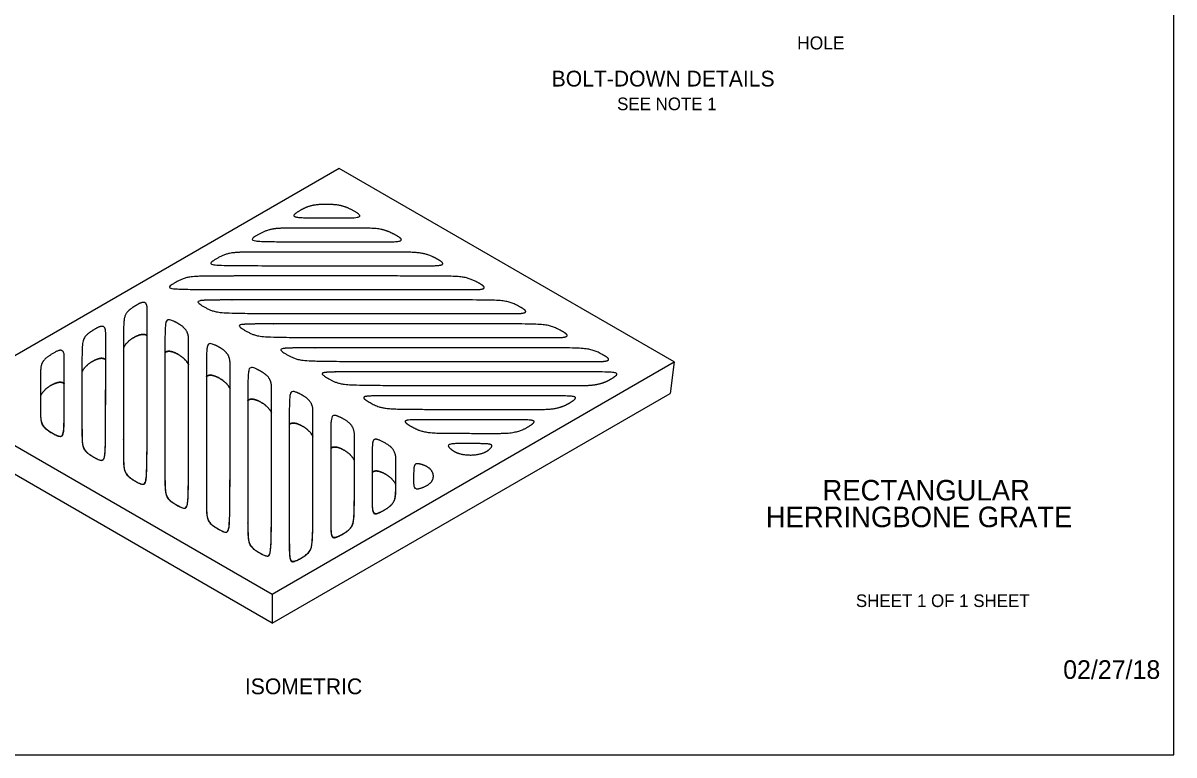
# Model space of a CAD drawing. Extents: x 99862 to 103151, y 100000 to 102076.
# Drawn here: x 101693 to 103151, y 100000 to 100926 of the extents above; entities that cross this region are included whole.
import ezdxf

# ---------------------------------------------------------------- set-up
doc = ezdxf.new("R2010")
doc.units = 0
for name, color, linetype in [('Level 1', 7, 'Continuous'), ('Level 2', 7, 'Continuous'), ('Level 20', 7, 'Continuous'), ('Level 6', 7, 'Continuous'), ('Level 62', 7, 'Continuous')]:
    doc.layers.add(name, color=color, linetype=linetype)

msp = doc.modelspace()

# ---------------------------------------------------------------- linework, layer by layer
at = {"layer": 'Level 1'}
msp.add_lwpolyline([(99862, 99999.5), (103151, 99999.5), (103151, 102075.5), (99862, 102075.5)], close=True, dxfattribs=at)
at = {"layer": 'Level 2'}
msp.add_line((101584.8, 100448.1), (102009.1, 100203.1), dxfattribs=at)
for points, degree in [([(102106.7, 100679.5), (102078, 100679.5), (102049.2, 100679.5), (102028.7, 100679.5), (102042.7, 100687.9), (102056.7, 100696.3), (102078, 100696.8), (102099.5, 100696.3), (102113.4, 100687.9), (102127.3, 100679.5), (102106.7, 100679.5)], 4), ([(102159.2, 100649.2), (102078, 100649.2), (101996.7, 100649.2), (101975.6, 100649.2), (101990.6, 100657.9), (102005.6, 100666.5), (102026.8, 100666.5), (102078.1, 100666.5), (102129.4, 100666.5), (102150.6, 100666.5), (102165.5, 100657.8), (102180.4, 100649.2), (102159.2, 100649.2)], 4), ([(102211.7, 100618.9), (102078, 100618.9), (101944.2, 100618.9), (101923.1, 100618.9), (101938.1, 100627.6), (101953.1, 100636.2), (101974.3, 100636.2), (102078.1, 100636.2), (102181.9, 100636.2), (102203.1, 100636.1), (102218, 100627.5), (102232.9, 100618.9), (102211.7, 100618.9)], 4), ([(102264.2, 100588.6), (102078, 100588.6), (101891.8, 100588.6), (101870.6, 100588.6), (101885.6, 100597.2), (101900.6, 100605.9), (101921.8, 100605.9), (102078.1, 100605.9), (102234.4, 100605.9), (102255.6, 100605.8), (102270.5, 100597.2), (102285.4, 100588.6), (102264.2, 100588.6)], 4), ([(101850.6, 100564.8), (101850.6, 100457.3), (101850.6, 100349.7), (101850.6, 100337.5), (101835.6, 100346.1), (101820.7, 100354.7), (101820.6, 100367), (101820.6, 100457.2), (101820.6, 100547.4), (101820.6, 100559.7), (101835.6, 100568.4), (101850.6, 100577), (101850.6, 100564.8)], 4), ([(102316.7, 100558.3), (102137.7, 100558.3), (101958.6, 100558.3), (101937.4, 100558.3), (101922.5, 100566.9), (101907.6, 100575.6), (101928.8, 100575.6), (102107.8, 100575.6), (102286.9, 100575.6), (102308.1, 100575.5), (102323, 100566.9), (102337.9, 100558.3), (102316.7, 100558.3)], 4), ([(101903.1, 100526.2), (101903.1, 100422.8), (101903.1, 100319.4), (101903.1, 100307.2), (101888.1, 100315.8), (101873.2, 100324.4), (101873.1, 100336.7), (101873.1, 100440.1), (101873.1, 100543.4), (101873.1, 100555.6), (101888, 100547), (101903, 100538.4), (101903.1, 100526.2)], 4), ([(102369.2, 100527.9), (102190.2, 100527.9), (102011.1, 100527.9), (101989.9, 100528), (101975, 100536.6), (101960.1, 100545.3), (101981.3, 100545.3), (102160.3, 100545.3), (102339.4, 100545.3), (102360.6, 100545.2), (102375.5, 100536.6), (102390.4, 100527.9), (102369.2, 100527.9)], 4), ([(101798.1, 100534.5), (101798.1, 100457.3), (101798.1, 100380.1), (101798.1, 100367.8), (101783.1, 100376.4), (101768.2, 100385), (101768.1, 100397.3), (101768.1, 100457.2), (101768.1, 100517.1), (101768.1, 100529.4), (101783, 100538), (101798, 100546.7), (101798.1, 100534.5)], 4), ([(101850.6, 100530), (101845.8, 100535.4), (101835.1, 100529.7), (101825.1, 100524.4), (101820.6, 100514.8)], 4), ([(101820.6, 100514.8), (101825.1, 100524.4), (101835.1, 100529.7), (101845.8, 100535.4), (101850.6, 100530)], 4), ([(101820.6, 100391.7), (101820.6, 100379.3), (101820.6, 100367), (101820.7, 100354.7), (101835.6, 100346.1), (101850.6, 100337.5), (101850.6, 100349.7), (101850.6, 100439.9), (101850.6, 100530)], 4), ([(101820.6, 100514.8), (101820.6, 100453.2), (101820.6, 100391.7)], 2), ([(101955.6, 100495.9), (101955.6, 100392.5), (101955.6, 100289.1), (101955.6, 100276.9), (101940.6, 100285.5), (101925.7, 100294.1), (101925.6, 100306.4), (101925.6, 100409.7), (101925.6, 100513.1), (101925.6, 100525.3), (101940.5, 100516.7), (101955.5, 100508.1), (101955.6, 100495.9)], 4), ([(102421.7, 100497.6), (102242.7, 100497.6), (102063.6, 100497.6), (102042.4, 100497.7), (102027.5, 100506.3), (102012.6, 100515), (102033.8, 100515), (102212.8, 100515), (102391.9, 100515), (102413.1, 100514.9), (102428, 100506.3), (102442.9, 100497.6), (102421.7, 100497.6)], 4), ([(101745.6, 100504.2), (101745.6, 100457.3), (101745.6, 100410.4), (101745.6, 100398.2), (101730.6, 100406.8), (101715.7, 100415.4), (101715.6, 100427.6), (101715.6, 100457.2), (101715.6, 100486.8), (101715.6, 100499), (101730.5, 100507.7), (101745.5, 100516.4), (101745.6, 100504.2)], 4), ([(101798.1, 100499.7), (101793.3, 100505.1), (101782.6, 100499.4), (101772.5, 100494), (101768.1, 100484.4)], 4), ([(101768.1, 100484.4), (101772.5, 100494), (101782.6, 100499.4), (101793.3, 100505.1), (101798.1, 100499.7)], 4), ([(101768.1, 100413.7), (101768.1, 100405.5), (101768.1, 100397.3), (101768.2, 100385), (101783.1, 100376.4), (101798.1, 100367.8), (101798.1, 100380.1), (101798.1, 100439.9), (101798.1, 100499.7)], 4), ([(101903.1, 100493.4), (101898.6, 100503), (101888.5, 100508.4), (101877.8, 100514), (101873.1, 100508.6)], 4), ([(101873.1, 100508.6), (101877.8, 100514), (101888.5, 100508.4), (101898.6, 100503), (101903.1, 100493.4)], 4), ([(101873.1, 100508.6), (101873.1, 100436.8), (101873.1, 100365)], 2), ([(101873.1, 100365), (101873.1, 100350.8), (101873.1, 100336.7), (101873.2, 100324.4), (101888.1, 100315.8), (101903.1, 100307.2), (101903.1, 100319.4), (101903.1, 100406.4), (101903.1, 100493.4)], 4), ([(102008.1, 100465.6), (102008.1, 100362.2), (102008.1, 100258.8), (102008.1, 100246.6), (101993.1, 100255.2), (101978.2, 100263.8), (101978.1, 100276.1), (101978.1, 100379.4), (101978.1, 100482.8), (101978.1, 100495), (101993, 100486.4), (102008, 100477.8), (102008.1, 100465.6)], 4), ([(101745.6, 100469.4), (101740.8, 100474.8), (101730.1, 100469), (101720, 100463.7), (101715.6, 100454.1)], 4), ([(101715.6, 100454.1), (101720, 100463.7), (101730.1, 100469), (101740.8, 100474.8), (101745.6, 100469.4)], 4), ([(101768.1, 100484.4), (101768.1, 100449.1), (101768.1, 100413.7)], 2), ([(101955.6, 100463.1), (101951.1, 100472.7), (101941, 100478.1), (101930.3, 100483.7), (101925.6, 100478.3)], 4), ([(101925.6, 100478.3), (101930.3, 100483.7), (101941, 100478.1), (101951.1, 100472.7), (101955.6, 100463.1)], 4), ([(101925.6, 100478.3), (101925.6, 100406.5), (101925.6, 100334.7)], 2), ([(102403.1, 100467.3), (102259.6, 100467.3), (102116.1, 100467.3), (102094.9, 100467.4), (102080, 100476), (102065.1, 100484.6), (102086.3, 100484.6), (102259.7, 100484.6), (102433.2, 100484.6), (102454.3, 100484.6), (102439.2, 100476), (102424.2, 100467.3), (102403.1, 100467.3)], 4), ([(101715.6, 100435.7), (101715.6, 100431.7), (101715.6, 100427.6), (101715.7, 100415.4), (101730.6, 100406.8), (101745.6, 100398.2), (101745.6, 100410.4), (101745.6, 100439.9), (101745.6, 100469.4)], 4), ([(101925.6, 100334.7), (101925.6, 100320.5), (101925.6, 100306.4), (101925.7, 100294.1), (101940.6, 100285.5), (101955.6, 100276.9), (101955.6, 100289.1), (101955.6, 100376.1), (101955.6, 100463.1)], 4), ([(102060.6, 100435.2), (102060.6, 100352.4), (102060.6, 100269.6), (102060.6, 100257.4), (102045.6, 100248.7), (102030.7, 100240), (102030.6, 100252.2), (102030.6, 100352.3), (102030.6, 100452.5), (102030.6, 100464.7), (102045.5, 100456.1), (102060.5, 100447.5), (102060.6, 100435.2)], 4), ([(101715.6, 100454.1), (101715.6, 100444.9), (101715.6, 100435.7)], 2), ([(102008.1, 100432.8), (102003.6, 100442.4), (101993.5, 100447.7), (101982.8, 100453.4), (101978.1, 100448)], 4), ([(101978.1, 100448), (101982.8, 100453.4), (101993.5, 100447.7), (102003.6, 100442.4), (102008.1, 100432.8)], 4), ([(101978.1, 100448), (101978.1, 100376.2), (101978.1, 100304.4)], 2), ([(102350.6, 100437), (102259.6, 100437), (102168.6, 100437), (102147.4, 100437.1), (102132.5, 100445.7), (102117.6, 100454.3), (102138.8, 100454.3), (102259.7, 100454.3), (102380.7, 100454.3), (102401.8, 100454.3), (102386.7, 100445.6), (102371.7, 100437), (102350.6, 100437)], 4), ([(101978.1, 100304.4), (101978.1, 100290.2), (101978.1, 100276.1), (101978.2, 100263.8), (101993.1, 100255.2), (102008.1, 100246.6), (102008.1, 100258.8), (102008.1, 100345.8), (102008.1, 100432.8)], 4), ([(102113.1, 100404.9), (102113.1, 100352.4), (102113.1, 100299.9), (102113.1, 100287.7), (102098.1, 100279), (102083.2, 100270.4), (102083.1, 100282.5), (102083.1, 100352.3), (102083.1, 100422.2), (102083.1, 100434.4), (102098, 100425.8), (102113, 100417.2), (102113.1, 100404.9)], 4), ([(102060.6, 100402.5), (102056.1, 100412.1), (102046, 100417.4), (102035.3, 100423.1), (102030.6, 100417.7)], 4), ([(102030.6, 100417.7), (102035.3, 100423.1), (102046, 100417.4), (102056.1, 100412.1), (102060.6, 100402.5)], 4), ([(102030.6, 100417.7), (102030.6, 100348.7), (102030.6, 100279.6)], 2), ([(102298.1, 100406.7), (102259.6, 100406.7), (102221.1, 100406.7), (102199.9, 100406.8), (102185, 100415.4), (102170.1, 100424), (102191.3, 100424), (102259.7, 100424), (102328.2, 100424), (102349.2, 100424), (102334.2, 100415.3), (102319.2, 100406.7), (102298.1, 100406.7)], 4), ([(102030.6, 100279.6), (102030.6, 100265.9), (102030.6, 100252.2), (102030.7, 100240), (102045.6, 100248.7), (102060.6, 100257.4), (102060.6, 100269.6), (102060.6, 100336), (102060.6, 100402.5)], 4), ([(102165.6, 100374.6), (102165.6, 100352.4), (102165.6, 100330.2), (102165.6, 100318), (102150.6, 100309.3), (102135.7, 100300.7), (102135.6, 100312.8), (102135.6, 100352.3), (102135.6, 100391.9), (102135.6, 100404.1), (102150.5, 100395.5), (102165.5, 100386.9), (102165.6, 100374.6)], 4), ([(102113.1, 100372.2), (102108.6, 100381.8), (102098.5, 100387.1), (102087.8, 100392.8), (102083.1, 100387.4)], 4), ([(102083.1, 100387.4), (102087.8, 100392.8), (102098.5, 100387.1), (102108.6, 100381.8), (102113.1, 100372.2)], 4), ([(102083.1, 100387.4), (102083.1, 100344.5), (102083.1, 100301.6)], 2), ([(102243.8, 100393.7), (102259.7, 100393.7), (102275.7, 100393.7), (102291.4, 100393.7), (102285.2, 100387.5), (102278.9, 100381.3), (102259.7, 100377.8), (102240.3, 100381.4), (102234.1, 100387.5), (102228, 100393.7), (102243.8, 100393.7)], 4), ([(102083.1, 100301.6), (102083.1, 100292.1), (102083.1, 100282.5), (102083.2, 100270.4), (102098.1, 100279), (102113.1, 100287.7), (102113.1, 100299.9), (102113.1, 100336), (102113.1, 100372.2)], 4), ([(102188.1, 100343.1), (102188.1, 100352.3), (102188.1, 100361.6), (102188.1, 100370.7), (102198.8, 100367.1), (102209.5, 100363.5), (102215.6, 100352.4), (102209.5, 100341.3), (102198.8, 100337.7), (102188.1, 100334.1), (102188.1, 100343.1)], 4), ([(102165.6, 100341.9), (102161.1, 100351.5), (102151, 100356.8), (102140.3, 100362.4), (102135.6, 100357.1)], 4), ([(102135.6, 100357.1), (102140.3, 100362.4), (102151, 100356.8), (102161.1, 100351.5), (102165.6, 100341.9)], 4), ([(102135.6, 100357.1), (102135.6, 100340.4), (102135.6, 100323.6)], 2), ([(102135.6, 100323.6), (102135.6, 100318.2), (102135.6, 100312.8), (102135.7, 100300.7), (102150.6, 100309.3), (102165.6, 100318), (102165.6, 100330.2), (102165.6, 100336), (102165.6, 100341.9)], 4)]:
    msp.add_open_spline(points, degree=degree, dxfattribs=at)
at = {"layer": 'Level 6'}
for p, q in [((102009.1, 100203.1), (102518.2, 100497.1)), ((102518.2, 100497.1), (102512.9, 100457.3)), ((102009.1, 100203.1), (102009.1, 100166.4))]:
    msp.add_line(p, q, dxfattribs=at)
for points in [[(102518.2, 100497.1), (102518.2, 100497.1), (102093.9, 100742), (101584.8, 100448.1)], [(102009.1, 100166.4), (102009.1, 100166.4), (102512.9, 100457.3)], [(102009.1, 100166.4), (102009.1, 100166.4), (101590.1, 100408.3), (101584.8, 100448.1)]]:
    msp.add_lwpolyline(points, dxfattribs=at)

# ---------------------------------------------------------------- texts
at = {"layer": 'Level 1'}
msp.add_text('HOLE', height=16.5, dxfattribs=at).set_placement((102673.7, 100892.7))
at = {"layer": 'Level 20'}
for s, p in [('BOLT-DOWN DETAILS', (102362.9, 100845.8)), ('ISOMETRIC', (101974.4, 100076.4))]:
    msp.add_text(s, height=20, dxfattribs=at).set_placement(p)
at = {"layer": 'Level 62'}
for s, height, p in [('SEE NOTE 1', 16, (102445.8, 100815.8)), ('RECTANGULAR', 26, (102705.8, 100321.7)), ('HERRINGBONE GRATE', 26, (102634, 100287.9)), ('SHEET 1 OF 1 SHEET', 16, (102748.2, 100186.8)), ('02/27/18', 23.62, (103010.7, 100095.8))]:
    msp.add_text(s, height=height, dxfattribs=at).set_placement(p)

doc.saveas('drawing.dxf')
